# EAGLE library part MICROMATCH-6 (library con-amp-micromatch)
MicroMaTch 6 7-215464-6 / 0-215464-6 Drawing Number C-215464 DDEController.pdf
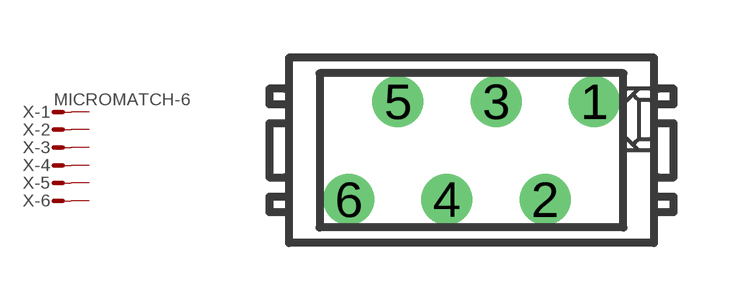
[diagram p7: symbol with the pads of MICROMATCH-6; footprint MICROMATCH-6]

Designator prefix X; gates -1=MV -2=M -3=M -4=M -5=M -6=M

## MICROMATCH-6 (MPN: 7-215464-6; OC_FARNELL: 3784630; OC_NEWARK: 19R8125)  [MICROMATCH-6]
1  -1:S  pas
2  -2:S  pas
3  -3:S  pas
4  -4:S  pas
5  -5:S  pas
6  -6:S  pas

## Footprint MICROMATCH-6 (pad centres in mm)
MicroMaTch 6 7-215464-6 / 0-215464-6 Drawing Number C-215464 DDEController.pdf
drill 0.813 round: 1 3.175,1.27; 2 1.905,-1.27; 3 0.635,1.27; 4 -0.635,-1.27; 5 -1.905,1.27; 6 -3.175,-1.27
